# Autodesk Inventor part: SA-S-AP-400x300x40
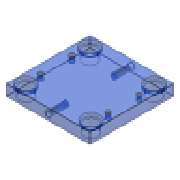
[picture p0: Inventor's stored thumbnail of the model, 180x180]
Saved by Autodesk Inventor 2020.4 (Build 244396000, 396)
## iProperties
Created: 2019-01
Part Number: SA-S-AP-400x300x40
Material: S 55 C
Description: Cavity Plate
Document SubType Name: Modeling
Designer: mel
Standard Revision: 1
Manufacturer: FUTABA
Language: fr-FR
Size Designation: 400x300x40
Categories: <MemberInstance><Categories><Category DisplayName="Moule" InternalName="349578f2-f4d4-4954-8c09-8e99297a61c0" Mnemonic="MOLD"><Category DisplayName="Plaque de m
Density: 7.85 g/cm^3
Appearance: Clear - Blue
IsCustomPart: 1
Author: mel
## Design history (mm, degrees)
sketch "Sketch1"
  geometry: L1 (-150, 200)-(150, 200); L2 (150, 200)-(150, -200); L3 (150, -200)-(-150, -200); L4 (-150, -200)-(-150, 200); 3 further points
  constraints: 8 end point, 2 midpoint, 2 parallel, 1 horizontal, 1 horizontal alignment, 1 perpendicular, 1 vertical alignment
  dimensions: "d123" = 300 distance between parallel lines of L2 L4 (= W_); "d124" = 400 distance between parallel lines of L3 L1 (= L)
extrude "Extrusion1" new body sketch "Sketch1" distance "d20" = 40 (= H_); taper "d30" = 0 deg
sketch "Sketch2"
  geometry: 4 further points
  constraints: 1 horizontal alignment
  dimensions: "d125" = 120 horizontal distance of point (0, 0) point (-120, 119) (= 0.5 x S1_W); "d126" = 119 vertical distance of point (0, 0) point (-120, 119) (= 0.5 x S1_L); "d127" = 117 horizontal distance of point (0, 0) point (-117, 167) (= 0.5 x GB_W); "d128" = 167 vertical distance of point (0, 0) point (-117, 167) (= 0.5 x GB_L); "d129" = 117 horizontal distance of point (0, 0) point (117, 167) (= 0.5 x GB_W)
sketch "Sketch3"
  geometry: L1 (300, 0)-(0, 0) reference; 3 further points
  constraints: 1 midpoint, 1 vertical alignment
  dimensions: "d169" = 20 distance from line of L1 point (150, 20) (= 0.5 x H_)
hole "Hole1" sketch "Sketch3" at (150, 20) diameter "d170" = 17.294; stored, may be unused: countersink angle "d174" = 90 deg, drill point angle "d176" = 118 deg; dims "d171" = 33 (= le), "d172" = 4, "d173" = 2, "d175" = 46 (= ke)
sketch "Sketch4"
  geometry: L1 (0, 0)-(300, 0) reference; 4 further points
  constraints: 2 midpoint, 2 vertical alignment
  dimensions: "d177" = 20 distance from line of L1 point (150, -20) (= 0.5 x H_)
hole "Hole2" sketch "Sketch4" at (150, -20) diameter "d178" = 17.294; stored, may be unused: countersink angle "d182" = 90 deg, drill point angle "d184" = 118 deg; dims "d179" = 33 (= le), "d180" = 4, "d181" = 2, "d183" = 46 (= ke)
hole "Hole3" sketch "Sketch2" diameter "d130" = 42 (= GB_d1); stored, may be unused: countersink angle "d134" = 90 deg, drill point angle "d136" = 0 deg; dims "d131" = 6, "d132" = 48 (= GB_d2), "d133" = 10 (= GB_k), "d135" = 40 (= H_)
pattern_linear "Rectangular Pattern1" dims "d159" = 334 (computed from GB_L, Nl)
hole "Hole4" sketch "Sketch2" diameter "d137" = 42 (= GB_d1); stored, may be unused: countersink angle "d141" = 90 deg, drill point angle "d143" = 0 deg; dims "d138" = 6, "d139" = 48 (= GB_d2), "d140" = 10 (= GB_k), "d142" = 40 (= H_)
pattern_linear "Rectangular Pattern2" dims "d162" = 332 (computed from GB_L2, GB_L1, Nl)
hole "Hole5" sketch "Sketch2" diameter "d144" = 11.835; stored, may be unused: countersink angle "d148" = 90 deg, drill point angle "d150" = 118 deg; dims "d145" = 18 (= H_l), "d146" = 48 (= GB_d2), "d147" = 10 (= GB_k), "d149" = 28 (= H_u)
pattern_linear "Rectangular Pattern3" dims "d153" = 119 (computed from S1_L, Ns), "d156" = 240 (computed from S1_W, Nw)
chamfer "Chamfer1" distance "d185" = 0.5; stored, may be unused: second distance "d186" = 2, angle "d187" = 45 deg
feature "Sculpter1"
body "Solid1"
feature "Surface1"
body "Srf1"
other parameters: "L" = 400 [user parameter; used in 1 equation term], "W_" = 300 [user parameter; used in 1 equation term], "H_" = 40 [user parameter; used in 5 equation terms], "GB_W" = 234 [user parameter; used in 2 equation terms], "GB_d1" = 42 [user parameter; used in 2 equation terms], "GB_d2" = 48 [user parameter; used in 3 equation terms], "GB_k" = 10 [user parameter; used in 3 equation terms], "S1_L" = 238 [user parameter; used in 2 equation terms], "GB_L1" = 167 [user parameter; used in 1 equation term], "GB_L2" = 165 [user parameter; used in 1 equation term], "GB_L" = 334 [user parameter; used in 2 equation terms], "le" = 33 [user parameter; used in 2 equation terms], "ke" = 46 [user parameter; used in 2 equation terms], "H_l" = 18 [user parameter; used in 1 equation term], "H_u" = 28 [user parameter; used in 1 equation term]
